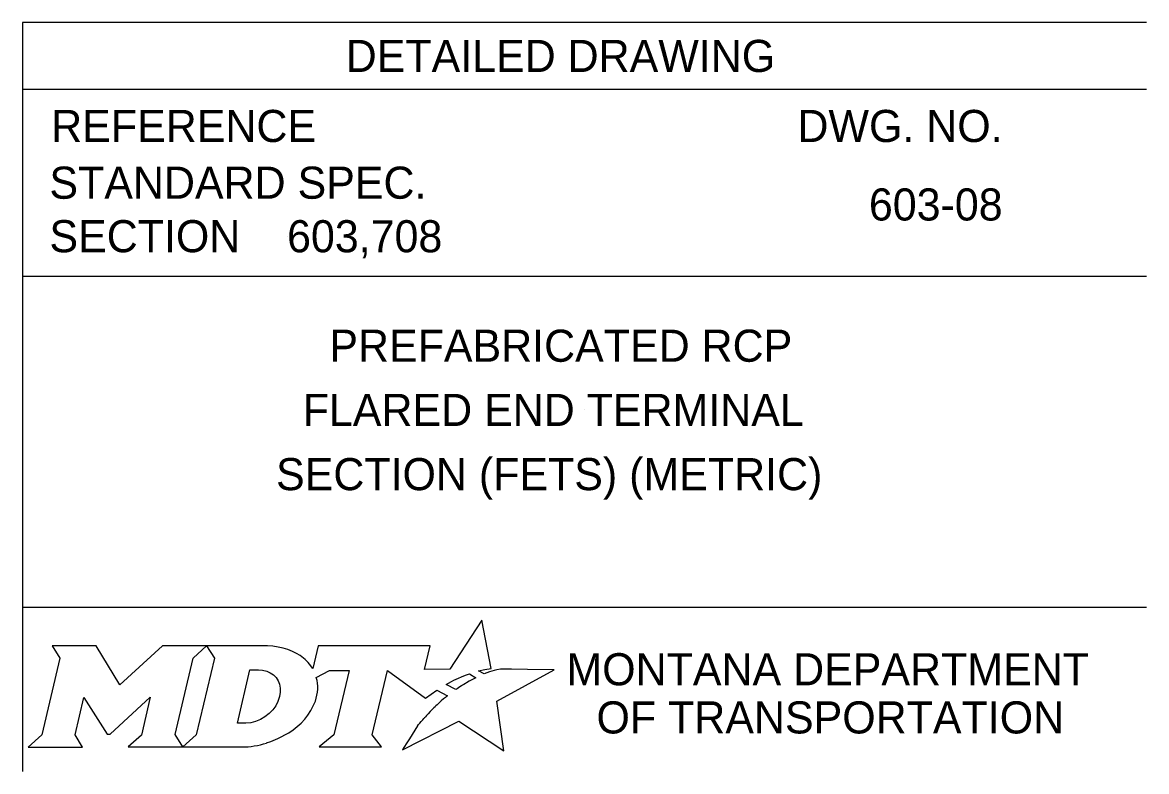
# Model space of a CAD drawing. Extents: x 49991.4 to 50022.1, y 49985 to 50011.4.
# Drawn here: x 50019.985 to 50022.085, y 49984.985 to 49986.385 of the extents above; entities that cross this region are included whole.
import ezdxf

# ---------------------------------------------------------------- set-up
doc = ezdxf.new("R2010")
doc.units = 0
for name, color, linetype in [('Default', 7, 'Continuous'), ('Level 2', 7, 'Continuous'), ('Level 5', 7, 'Continuous')]:
    doc.layers.add(name, color=color, linetype=linetype)

msp = doc.modelspace()

# ---------------------------------------------------------------- linework, layer by layer
at = {"layer": 'Default'}
for points in [[(50020.8477, 49985.1675), (50020.8373, 49985.1731), (50020.849, 49985.1759), (50020.8606, 49985.1778), (50020.8432, 49985.2679), (50020.7837, 49985.1767), (50020.7364, 49985.1759), (50020.7467, 49985.22), (50020.5375, 49985.2202), (50020.5274, 49985.1776), (50020.5215, 49985.186)], [(50020.0407, 49985.2201), (50020.0547, 49985.1968), (50020.0213, 49985.0535), (50019.9956, 49985.0309), (50020.0972, 49985.0309), (50020.0836, 49985.0538), (50020.0998, 49985.1238), (50020.1436, 49985.0548), (50020.1489, 49985.0548), (50020.224, 49985.1243), (50020.2075, 49985.0532), (50020.1829, 49985.0312), (50020.2845, 49985.0312), (50020.2707, 49985.0546), (50020.3039, 49985.1969)], [(50020.3039, 49985.1969), (50020.3292, 49985.2201), (50020.2468, 49985.2201), (50020.1672, 49985.1472), (50020.1226, 49985.2199), (50020.0407, 49985.2201)], [(50020.4428, 49985.2201), (50020.3292, 49985.2201), (50020.3439, 49985.1973), (50020.3099, 49985.0535), (50020.2845, 49985.0312), (50020.3951, 49985.0312)], [(50020.4668, 49985.1334), (50020.4656, 49985.1253), (50020.4624, 49985.1161), (50020.4582, 49985.1079), (50020.4526, 49985.1003), (50020.4461, 49985.0935), (50020.4381, 49985.0872), (50020.4298, 49985.0824), (50020.4208, 49985.0786), (50020.4116, 49985.0763), (50020.4025, 49985.0754), (50020.3866, 49985.0754), (50020.4102, 49985.1753), (50020.4261, 49985.1753), (50020.4338, 49985.1748), (50020.4414, 49985.1728), (50020.448, 49985.1698), (50020.4541, 49985.1657), (50020.4589, 49985.1606), (50020.4626, 49985.1547), (50020.4653, 49985.1484), (50020.4668, 49985.141), (50020.4669, 49985.138), (50020.4668, 49985.1334)], [(50020.5341, 49985.1611), (50020.5588, 49985.1741), (50020.5957, 49985.1741), (50020.5671, 49985.0537), (50020.5396, 49985.031), (50020.6558, 49985.031), (50020.6387, 49985.0538), (50020.667, 49985.174), (50020.7383, 49985.1224), (50020.7594, 49985.1374), (50020.7791, 49985.1265)], [(50020.7233, 49985.0706), (50020.708, 49985.0462), (50020.7033, 49985.0387), (50020.6975, 49985.0301), (50020.6952, 49985.0258), (50020.8005, 49985.079), (50020.8844, 49985.0239), (50020.8712, 49985.1165), (50020.9782, 49985.175), (50020.9289, 49985.1757), (50020.8988, 49985.1762), (50020.878, 49985.1765), (50020.8712, 49985.1749), (50020.8662, 49985.1737), (50020.8579, 49985.1714), (50020.8477, 49985.1675)], [(50020.7973, 49985.1399), (50020.7949, 49985.1382), (50020.7766, 49985.1477), (50020.7868, 49985.1535), (50020.7909, 49985.1557), (50020.7996, 49985.1596), (50020.8052, 49985.1622), (50020.8131, 49985.1653), (50020.8205, 49985.168), (50020.8323, 49985.1605), (50020.8283, 49985.1584), (50020.8237, 49985.156), (50020.8195, 49985.1538), (50020.8145, 49985.1509), (50020.8126, 49985.1498), (50020.8099, 49985.1481), (50020.8074, 49985.1467), (50020.8051, 49985.1451), (50020.8025, 49985.1433), (50020.7998, 49985.1416), (50020.7973, 49985.1399)], [(50020.7372, 49985.0867), (50020.7372, 49985.0867)], [(50020.4408, 49985.0385), (50020.4492, 49985.0411), (50020.4621, 49985.0466), (50020.4826, 49985.0575)]]:
    msp.add_lwpolyline(points, dxfattribs=at)
for centre, radius, start, end in [((50020.4659, 49985.1417), 0.0709, 339.5329, 15.8582), ((50020.4218, 49985.159), 0.1183, 300.9103, 339.1383)]:
    msp.add_arc(centre, radius, start, end, dxfattribs=at)
for centre, major_axis, ratio, start_param, end_param in [((50020.4407, 49985.1727), (0.0834, -0.0037), 0.568097, 0.61298, 1.570796), ((50020.4963, 49985.18), (0.0361, -0.0295), 0.469099, 1.225588, 1.570796), ((50020.7679, 49985.1168), (-0.0112, -0.0097), 0.021651, 3.157348, 6.283185), ((50020.747, 49985.0969), (-0.0098, -0.0102), 0.016458, 3.141593, 6.279097), ((50020.7302, 49985.0787), (-0.00694, -0.00806), 0.008222, 0, 3.137361), ((50020.3954, 49985.1795), (0, 0.1484), 0.987302, 3.139398, 3.456847)]:
    msp.add_ellipse(centre, major_axis=major_axis, ratio=ratio, start_param=start_param, end_param=end_param, dxfattribs=at)
at = {"layer": 'Level 5'}
for p, q in [((50022.0852, 49986.3851), (50019.9852, 49986.3851)), ((50019.9852, 49986.3851), (50019.9852, 49984.9851)), ((50022.0852, 49986.2601), (50019.9852, 49986.2601)), ((50021.7213, 49986.045), (50021.7213, 49986.045)), ((50020.4795, 49985.9856), (50020.4795, 49985.9856)), ((50022.0852, 49985.9101), (50019.9852, 49985.9101)), ((50021.0352, 49985.661), (50021.0352, 49985.661)), ((50022.0852, 49985.292), (50019.9852, 49985.292))]:
    msp.add_line(p, q, dxfattribs=at)

# ---------------------------------------------------------------- texts
at = {"layer": 'Default'}
for s, p in [('MONTANA DEPARTMENT', (50021.0014, 49985.1463)), ('OF TRANSPORTATION', (50021.0576, 49985.0563))]:
    msp.add_text(s, height=0.06, rotation=360, dxfattribs=at).set_placement(p)
at = {"layer": 'Level 2'}
for s, p in [('603-08', (50021.5665, 49986.015)), ('603,708', (50020.4795, 49985.9556)), ('PREFABRICATED RCP', (50020.5585, 49985.751)), ('FLARED END TERMINAL', (50020.5087, 49985.631)), ('SECTION (FETS) (METRIC)', (50020.4589, 49985.511))]:
    msp.add_text(s, height=0.06, dxfattribs=at).set_placement(p)
at = {"layer": 'Level 5'}
for s, p in [('DETAILED DRAWING', (50020.589, 49986.2926)), ('REFERENCE', (50020.0388, 49986.1617)), ('DWG. NO.', (50021.433, 49986.1617)), ('STANDARD SPEC.', (50020.0355, 49986.0557)), ('SECTION', (50020.0355, 49985.9557))]:
    msp.add_text(s, height=0.06, dxfattribs=at).set_placement(p)

doc.saveas('drawing.dxf')
